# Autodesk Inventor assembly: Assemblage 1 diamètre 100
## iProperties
Shininess: 64.0
Length Units: 11269
Angle Units: 11279
Time Units: 11290
Mass Units: 11283
Length Display Precision: 3
Angle Display Precision: 2
Compacted: True
Created: 2006-01
Part Number: Assemblage 1 diamètre 100
Document SubType Name: Assembly
Designer: riri
Density: 0.0
Volumn: 0.0
Area: 0.0
PropertySet Name: Model Information
Control State: 0
Master: False
Checked Out: False
Norme de conversion: STEP AP214DIS
Nom du fichier: Assemblage 1 diamètre 100.STEP
Préprocesseur: SolidWorks 2003099
Postprocesseur: Build: 120c, Release: 6 SP2 - Date: Mon 01/13/2003
Unités envoyées: MILLIMETERS
Incertitude: 0.0
Author: riri
